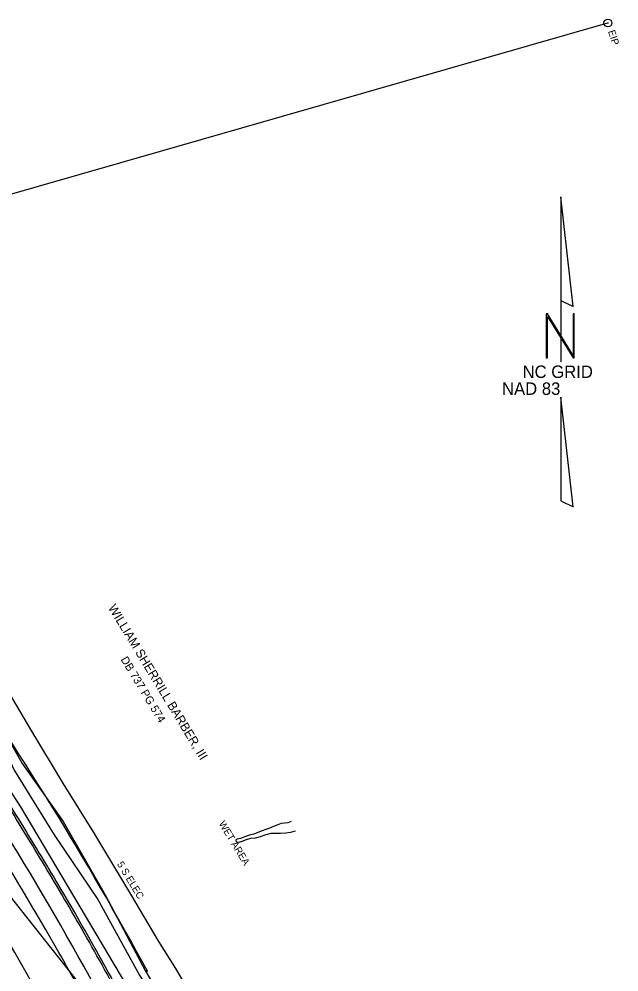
# Model space of a CAD drawing. Extents: x 1498375 to 1499839, y 700490 to 702854.
# Drawn here: x 1498995 to 1499332, y 702024 to 702560 of the extents above; entities that cross this region are included whole.
import ezdxf

# ---------------------------------------------------------------- set-up
doc = ezdxf.new("R2010")
doc.units = 0
for name, color, linetype in [('CTL North Arrow NAD 83 CELL', 7, 'Continuous'), ('Exist Horizontal Alignment', 7, 'Continuous'), ('Exist Horizontal Baseline Alignment', 7, 'Continuous'), ('Exist Hydro Stream or Body of Water', 7, 'Continuous'), ('Exist Hydro Stream or Body of Water Text', 7, 'Continuous'), ('Exist Other Culture Fence Line', 7, 'Continuous'), ('Exist Other Culture Fence Line Text', 7, 'Continuous'), ('Exist Property Deed Book Text', 7, 'Continuous'), ('Exist Property Iron Pin CELL', 7, 'Continuous'), ('Exist Property Iron Pin Text', 7, 'Continuous'), ('Exist Property Line', 7, 'Continuous'), ('Exist Property Owner Text', 7, 'Continuous'), ('Exist Right of Way Line', 7, 'Continuous'), ('Exist Roads EOP', 7, 'Continuous'), ('Exist Utilities Telephone UG Cable', 7, 'Continuous')]:
    doc.layers.add(name, color=color, linetype=linetype)

# ---------------------------------------------------------------- blocks, each defined once
blk = doc.blocks.new('CTL NORTH ARROW NAD 83')
at = {"layer": 'CTL North Arrow NAD 83 CELL'}
for points in [[(0.001, 1.743), (0.001, 0.577), (0.139, 0.509)], [(-0.163, -0.068), (-0.149, -0.068), (-0.149, 0.399), (0.139, -0.068), (0.152, -0.068), (0.152, 0.426), (0.139, 0.426), (0.139, -0.041), (-0.149, 0.426), (-0.163, 0.426)], [(0.001, -1.673), (0.139, -1.742), (0.001, -0.507)]]:
    blk.add_lwpolyline(points, close=True, dxfattribs=at)
blk.add_lwpolyline([(0.001, 0.577), (0.001, -0.11)], dxfattribs=at)
for s, p in [('NC GRID', (-0.429, -0.293)), ('   NAD 83', (-0.816, -0.483))]:
    blk.add_text(s, height=0.14, dxfattribs=at).set_placement(p)
blk = doc.blocks.new('EXIST PROPERTY IRON PIN')
at = {"layer": 'Exist Property Iron Pin CELL'}
for radius in [0.0441, 0.00141]:
    blk.add_circle((0, 0), radius, dxfattribs=at)

msp = doc.modelspace()

# ---------------------------------------------------------------- linework, layer by layer
at = {"layer": 'Exist Horizontal Alignment'}
msp.add_arc((1497414.63, 701128.78), 1850, 28.43684, 41.64975, dxfattribs=at)
at = {"layer": 'Exist Horizontal Baseline Alignment'}
msp.add_line((1498656.97, 702485.84), (1499111.17, 701914.37), dxfattribs=at)
at = {"layer": 'Exist Hydro Stream or Body of Water'}
for points in [[(1498923.13, 702269.65), (1498946.97, 702226.68), (1498974.89, 702180.52), (1498997.28, 702141.2), (1499020.24, 702108.53), (1499043.88, 702067.32), (1499066.22, 702024.84), (1499088.67, 701987.1), (1499108.89, 701946.69), (1499130.74, 701912.55), (1499137.31, 701900.15), (1499148.26, 701890.97), (1499161.01, 701868.08)], [(1498920.64, 702267.7), (1498942.69, 702226.38), (1498973.32, 702178.73), (1498992.63, 702137.37), (1499015.19, 702101.1), (1499039.66, 702064.76), (1499063.39, 702021.83), (1499086.41, 701985.9), (1499106.94, 701945.16), (1499126.36, 701910.36), (1499134.81, 701898.16), (1499145.93, 701889.41), (1499158.48, 701865.97)], [(1499148.38, 702108.54), (1499146.53, 702107.83), (1499144.57, 702107.7), (1499142.77, 702107.44), (1499140.85, 702106.7), (1499138.75, 702105.88), (1499136.7, 702105.09), (1499134.63, 702104.29), (1499134.17, 702104.11), (1499132.09, 702103.31), (1499129.55, 702102.33), (1499127.37, 702101.53), (1499124.99, 702100.86), (1499122.64, 702100.08), (1499119.93, 702099.04), (1499118.04, 702098.66), (1499117.23, 702098.33), (1499117.47, 702097.08), (1499119.05, 702096.91), (1499120.77, 702097.53), (1499123.15, 702098.45), (1499125.62, 702099.11), (1499128.24, 702099.47), (1499131.05, 702100.13), (1499134.2, 702101.35), (1499137.15, 702102.09), (1499139.71, 702102.04), (1499142.42, 702102.04), (1499145.41, 702102.22), (1499148.07, 702102.65), (1499150.69, 702103.39)]]:
    msp.add_lwpolyline(points, dxfattribs=at)
at = {"layer": 'Exist Other Culture Fence Line'}
for points in [[(1498928.09, 702282.37), (1498939.01, 702264.82), (1498954.66, 702238.95), (1498969.22, 702214.71), (1498980, 702197.21), (1499001.83, 702160.26), (1499020.31, 702129.77), (1499037.3, 702102.31), (1499058.15, 702067.79), (1499073.87, 702041.2)], [(1499073.87, 702041.2), (1499083.36, 702025.9), (1499100.46, 701996.95), (1499138.77, 701934.83), (1499178.51, 701939.41), (1499178.51, 701939.41), (1499239.42, 701948.3), (1499295.19, 701943.49)]]:
    msp.add_lwpolyline(points, dxfattribs=at)
at = {"layer": 'Exist Property Line'}
msp.add_line((1498828.6, 702414.77), (1499326.3, 702557.3), dxfattribs=at)
at = {"layer": 'Exist Right of Way Line'}
for centre, radius, start, end in [((1497414.63, 701128.78), 1880, 28.43684, 41.64975), ((1497414.24, 701128.85), 1820.32, 28.42903, 41.4116)]:
    msp.add_arc(centre, radius, start, end, dxfattribs=at)
at = {"layer": 'Exist Roads EOP'}
for points in [[(1499091.1, 701936.52), (1499070.56, 701974.83), (1499049.05, 702015.25), (1499026.27, 702055.91), (1499004.38, 702092.76), (1498980.68, 702131.19), (1498955.1, 702169.98), (1498929.13, 702206.36), (1498901.23, 702244.8), (1498872.92, 702280.9), (1498841.61, 702319.53), (1498811.71, 702353.95), (1498782.02, 702388.2)], [(1499076.04, 701928.59), (1499055.35, 701966.79), (1499033.8, 702006.23), (1499010.35, 702048.03), (1498989.2, 702083.56), (1498965.39, 702121.96), (1498940.2, 702160.05), (1498914.57, 702197.35), (1498887.05, 702234.06), (1498859.77, 702269.48), (1498828.57, 702307.58), (1498798.2, 702342.6), (1498769.18, 702377.27)]]:
    msp.add_spline(points, degree=3, dxfattribs=at)
at = {"layer": 'Exist Utilities Telephone UG Cable'}
msp.add_lwpolyline([(1498893.62, 702261.31), (1498925.58, 702221.83), (1498960.51, 702171.63), (1498996.25, 702116.78), (1499118.37, 701910.93), (1499124.57, 701888.6)], dxfattribs=at)
msp.add_spline([(1498782.77, 702388.86), (1498812.47, 702354.61), (1498842.38, 702320.17), (1498873.7, 702281.52), (1498902.03, 702245.4), (1498929.94, 702206.94), (1498955.92, 702170.54), (1498981.52, 702131.72), (1499005.24, 702093.28), (1499027.14, 702056.41), (1499049.93, 702015.73), (1499071.44, 701975.3), (1499091.98, 701936.99)], degree=3, dxfattribs=at)

# ---------------------------------------------------------------- block references
at = {"layer": 'CTL North Arrow NAD 83 CELL', "xscale": 50, "yscale": 50}
msp.add_blockref('CTL NORTH ARROW NAD 83', (1499299.79, 702372.46), dxfattribs=at)
at = {"layer": 'Exist Property Iron Pin CELL', "xscale": 50, "yscale": 50}
msp.add_blockref('EXIST PROPERTY IRON PIN', (1499326.3, 702557.3), dxfattribs=at)

# ---------------------------------------------------------------- texts
at = {"layer": 'Exist Hydro Stream or Body of Water Text'}
msp.add_text('WET AREA', height=4, rotation=301.2023, dxfattribs=at).set_placement((1499107.44, 702107.37))
at = {"layer": 'Exist Other Culture Fence Line Text'}
msp.add_text('5 S ELEC', height=4, rotation=301.1244, dxfattribs=at).set_placement((1499050.32, 702084.63))
at = {"layer": 'Exist Property Deed Book Text'}
msp.add_text('DB 737 PG 574', height=4.5, rotation=301.2023, dxfattribs=at).set_placement((1499052.37, 702199.61))
at = {"layer": 'Exist Property Iron Pin Text'}
msp.add_text('EIP', height=4, rotation=287.9649, dxfattribs=at).set_placement((1499326.32, 702552.61))
at = {"layer": 'Exist Property Owner Text'}
msp.add_text('WILLIAM SHERRILL BARBER, III', height=5, rotation=301.2023, dxfattribs=at).set_placement((1499045.32, 702228.69))

doc.saveas('drawing.dxf')
